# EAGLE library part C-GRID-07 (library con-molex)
CONNECTOR wire to board 2.54 mm (0.100") pitch header
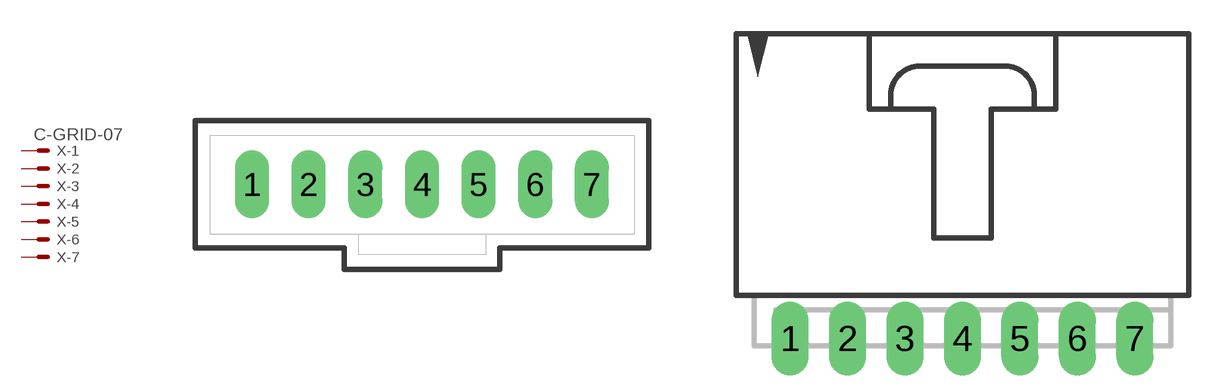
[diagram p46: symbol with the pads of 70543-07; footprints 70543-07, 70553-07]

Designator prefix X; gates -1=MV -2=M -3=M -4=M -5=M -6=M -7=M

## C-GRID-07-70543 (OC_FARNELL: unknown; OC_NEWARK: unknown)  [70543-07]
1  -1:S  pas
2  -2:S  pas
3  -3:S  pas
4  -4:S  pas
5  -5:S  pas
6  -6:S  pas
7  -7:S  pas

## C-GRID-07-70553 (OC_FARNELL: unknown; OC_NEWARK: unknown)  [70553-07]
Pads as for 70543-07

## C-GRID-07-74099 (OC_FARNELL: unknown; OC_NEWARK: unknown)  [74099-07]
Pads as for 70543-07

## C-GRID-07-15-91 (OC_FARNELL: unknown; OC_NEWARK: unknown)  [15-91-07]
Pads as for 70543-07

## Footprint 70543-07 (pad centres in mm)
C-Grid SL Connector vertical, 7 pin
drill 1.016 long: 1 -7.62,0; 2 -5.08,0; 3 -2.54,0; 4 0,0; 5 2.54,0; 6 5.08,0; 7 7.62,0

## Footprint 70553-07 (pad centres in mm)
C-Grid SL Connector right angle, 7 pin
drill 1.092 long: 1 -7.62,-7.62; 2 -5.08,-7.62; 3 -2.54,-7.62; 4 0,-7.62; 5 2.54,-7.62; 6 5.08,-7.62; 7 7.62,-7.62

## Footprint 74099-07 (pad centres in mm)
C-Grid SL Connector vertical SMD, 7 pin
smd 1.27 x 3.175: 1 -7.62,-2.223; 2 -5.08,2.223; 3 -2.54,-2.223; 4 0,2.223; 5 2.54,-2.223; 6 5.08,2.223; 7 7.62,-2.223

## Footprint 15-91-07 (pad centres in mm)
C-Grid SL Connector right angle SMD, 7 pin
smd 1.651 x 5.334: 1 -7.62,-10.795; 2 -5.08,-10.795; 3 -2.54,-10.795; 4 0,-10.795; 5 2.54,-10.795; 6 5.08,-10.795; 7 7.62,-10.795
hole 3.404 at -9.017,0.838
hole 3.404 at 9.017,0.838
